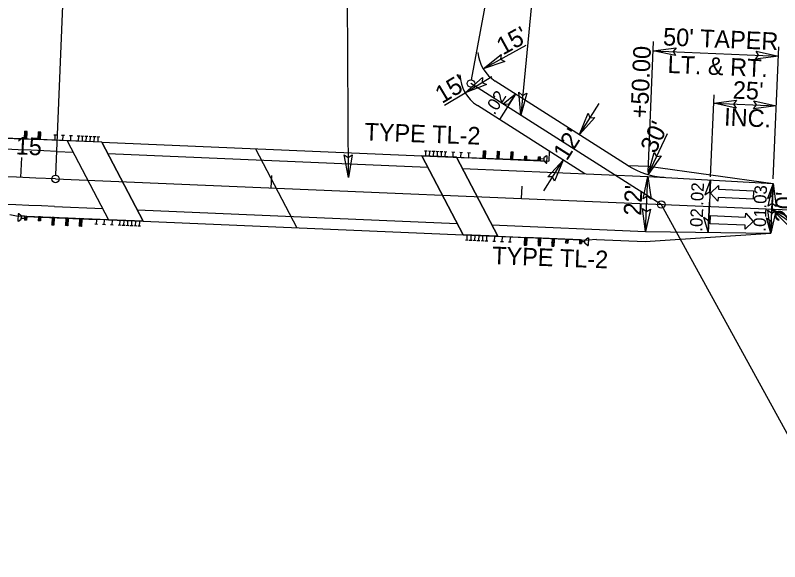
# Model space of a CAD drawing. Extents: x 2170295 to 2171718, y 723585 to 724580.
# Drawn here: x 2170898.6 to 2171203.6, y 723922.2 to 724140.1 of the extents above; entities that cross this region are included whole.
import ezdxf

# ---------------------------------------------------------------- set-up
doc = ezdxf.new("R2010")
doc.units = 0
for name, color, linetype in [('Prop Approach Slab', 7, 'Continuous'), ('Prop Approach Slab Hatching', 7, 'Continuous'), ('Prop Dimension', 7, 'Continuous'), ('Prop DSN Text', 7, 'Continuous'), ('Prop EOT', 7, 'Continuous'), ('Prop Guardrail', 7, 'Continuous'), ('Prop Guardrail Anchor Unit CELL', 7, 'Continuous'), ('Prop Horizontal Alignment', 7, 'Continuous'), ('Prop Horizontal Alignment Direction Label', 7, 'Continuous'), ('Prop Horizontal Alignment Station Label', 7, 'Continuous'), ('Prop Horizontal Alignment Tick Label', 7, 'Continuous'), ('Prop Horizontal Alignment Tick Large', 7, 'Continuous'), ('Prop Horizontal Alignment Tick Small', 7, 'Continuous'), ('Prop Lane Arrow CELL', 7, 'Continuous'), ('Prop Paved Shoulder', 7, 'Continuous'), ('Prop Roadway Bridge', 7, 'Continuous'), ('Prop Structure Anchor Unit CELL', 7, 'Continuous'), ('Prop Superelevation  Arrow CELL', 7, 'Continuous'), ('Prop Superelevation Label', 7, 'Continuous'), ('Prop Terminator CELL', 7, 'Continuous')]:
    doc.layers.add(name, color=color, linetype=linetype)

msp = doc.modelspace()

# ---------------------------------------------------------------- linework, layer by layer
at = {"layer": 'Prop Approach Slab'}
for p, q in [((2170933.16, 724089.46), (2170919.32, 724090.04)), ((2170919.32, 724090.04), (2170935.81, 724058.48)), ((2171060.1, 724084.1), (2171060.1, 724084.1)), ((2171060.79, 724084.07), (2171074.62, 724083.48)), ((2171074.62, 724083.48), (2171091.11, 724051.93)), ((2170949.64, 724057.9), (2170935.81, 724058.48)), ((2171091.11, 724051.93), (2171077.27, 724052.51))]:
    msp.add_line(p, q, dxfattribs=at)
at = {"layer": 'Prop Approach Slab Hatching'}
for points in [[(2170935.81, 724058.48), (2170949.64, 724057.9), (2170933.16, 724089.46), (2170919.32, 724090.04)], [(2171074.62, 724083.48), (2171060.79, 724084.07), (2171077.27, 724052.51), (2171091.11, 724051.93)]]:
    msp.add_lwpolyline(points, close=True, dxfattribs=at)
at = {"layer": 'Prop Dimension'}
for p, q in [((2171031.51, 724075.41), (2171030.57, 724264.51)), ((2171151.12, 724077.55), (2171153.32, 724129.63)), ((2171085.32, 724118.69), (2171102.5, 724128.16)), ((2171153.16, 724125.94), (2171203.12, 724123.83)), ((2171201.05, 724074.86), (2171203.28, 724127.52)), ((2171078.07, 724109.2), (2171088.79, 724115.68)), ((2171069.84, 724104.23), (2171078.07, 724109.2)), ((2171176.06, 724075.65), (2171177.44, 724108.29)), ((2171123.68, 724092.47), (2171131.54, 724104.86)), ((2171177.3, 724105.02), (2171202.28, 724103.96)), ((2171151.08, 724076.55), (2171158.83, 724092.95)), ((2171109.43, 724070.04), (2171117.25, 724082.34)), ((2171200.14, 724053.22), (2171200.97, 724072.93)), ((2171200.54, 724062.74), (2171439.97, 723895.67))]:
    msp.add_line(p, q, dxfattribs=at)
at = {"layer": 'Prop DSN Text'}
msp.add_line((2171150.12, 724053.86), (2171151.05, 724075.84), dxfattribs=at)
msp.add_line((2171150.12, 724053.86), (2171151.05, 724075.84), dxfattribs=at)
msp.add_line((2171150.12, 724053.86), (2171151.05, 724075.84), dxfattribs=at)
at = {"layer": 'Prop EOT'}
for p, q in [((2171143.19, 724080.08), (2171090.12, 724113.78)), ((2171125.82, 724076.9), (2171082.98, 724104.1)), ((2170915.08, 724085.8), (2170921.68, 724085.52)), ((2171076.98, 724078.96), (2171151.05, 724075.84)), ((2171151.05, 724075.84), (2171200.97, 724072.93)), ((2170914.15, 724063.82), (2170933.44, 724063)), ((2171088.75, 724056.45), (2171150.12, 724053.86)), ((2171150.12, 724053.86), (2171200.14, 724053.22))]:
    msp.add_line(p, q, dxfattribs=at)
for centre, radius, start, end in [((2171098.16, 724126.45), 15, 184.6964, 237.5825), ((2171091.02, 724116.76), 15, 181.901, 237.5825), ((2168445.99, 665601.01), 58536.88, 87.5825428, 87.7429222), ((2171159.27, 724105.41), 30, 237.5825, 266.6634), ((2168445.99, 665601.01), 58514.88, 87.5825428, 87.7429222)]:
    msp.add_arc(centre, radius, start, end, dxfattribs=at)
at = {"layer": 'Prop Guardrail'}
for p, q in [((2170914.43, 724090.25), (2170908.18, 724090.51)), ((2171085.76, 724083.01), (2171079.52, 724083.28)), ((2170924.67, 724058.95), (2170930.91, 724058.69)), ((2171096, 724051.72), (2171102.25, 724051.46))]:
    msp.add_line(p, q, dxfattribs=at)
at = {"layer": 'Prop Guardrail Anchor Unit CELL'}
for p, q in [((2170902.26, 724090.76), (2170902.38, 724093.79)), ((2170903.2, 724092.24), (2170902.26, 724090.76)), ((2170902.32, 724092.28), (2170903.26, 724093.76)), ((2170903.2, 724092.24), (2170902.32, 724092.28)), ((2170903.13, 724090.72), (2170902.32, 724092.28)), ((2170903.26, 724093.76), (2170902.38, 724093.79)), ((2170902.38, 724093.79), (2170903.2, 724092.24)), ((2170903.13, 724090.72), (2170903.26, 724093.76)), ((2170907.74, 724090.53), (2170907.87, 724093.56)), ((2170908.68, 724092.01), (2170907.74, 724090.53)), ((2170907.81, 724092.05), (2170908.75, 724093.52)), ((2170908.68, 724092.01), (2170907.81, 724092.05)), ((2170908.62, 724090.49), (2170907.81, 724092.05)), ((2170908.75, 724093.52), (2170907.87, 724093.56)), ((2170907.87, 724093.56), (2170908.68, 724092.01)), ((2170908.62, 724090.49), (2170908.75, 724093.52)), ((2170886.24, 724091.44), (2170908.18, 724090.51)), ((2170903.13, 724090.72), (2170902.26, 724090.76)), ((2170908.62, 724090.49), (2170907.74, 724090.53)), ((2171085.32, 724083.03), (2171085.45, 724086.06)), ((2171086.33, 724086.03), (2171085.39, 724084.55)), ((2171086.27, 724084.51), (2171085.45, 724086.06)), ((2171085.45, 724086.06), (2171086.33, 724086.03)), ((2171086.2, 724082.99), (2171086.33, 724086.03)), ((2171090.81, 724082.8), (2171090.94, 724085.83)), ((2171091.82, 724085.8), (2171090.87, 724084.32)), ((2171091.75, 724084.28), (2171090.94, 724085.83)), ((2171090.94, 724085.83), (2171091.82, 724085.8)), ((2171091.69, 724082.76), (2171091.82, 724085.8)), ((2171096.3, 724082.57), (2171096.42, 724085.6)), ((2171097.3, 724085.56), (2171096.36, 724084.09)), ((2171097.24, 724084.05), (2171096.42, 724085.6)), ((2171096.42, 724085.6), (2171097.3, 724085.56)), ((2171097.17, 724082.53), (2171097.3, 724085.56)), ((2171085.32, 724083.03), (2171086.27, 724084.51)), ((2171085.32, 724083.03), (2171086.2, 724082.99)), ((2171085.39, 724084.55), (2171086.27, 724084.51)), ((2171085.39, 724084.55), (2171086.2, 724082.99)), ((2171107.71, 724082.09), (2171085.76, 724083.01)), ((2171090.81, 724082.8), (2171091.75, 724084.28)), ((2171090.81, 724082.8), (2171091.69, 724082.76)), ((2171090.87, 724084.32), (2171091.75, 724084.28)), ((2171090.87, 724084.32), (2171091.69, 724082.76)), ((2171096.3, 724082.57), (2171097.24, 724084.05)), ((2171096.3, 724082.57), (2171097.17, 724082.53)), ((2171096.36, 724084.09), (2171097.24, 724084.05)), ((2171096.36, 724084.09), (2171097.17, 724082.53)), ((2171101.78, 724082.34), (2171101.85, 724083.85)), ((2171101.78, 724082.34), (2171102.73, 724083.82)), ((2171101.85, 724083.85), (2171102.72, 724083.82)), ((2171101.85, 724083.85), (2171102.66, 724082.3)), ((2171102.66, 724082.3), (2171102.72, 724083.82)), ((2171107.27, 724082.11), (2171107.33, 724083.62)), ((2171107.27, 724082.11), (2171108.21, 724083.58)), ((2171107.33, 724083.62), (2171108.21, 724083.58)), ((2171107.33, 724083.62), (2171108.15, 724082.07)), ((2171108.15, 724082.07), (2171108.21, 724083.58)), ((2171109.47, 724082.75), (2171108.18, 724082.8)), ((2171109.49, 724083.25), (2171109.44, 724082.03)), ((2171110.56, 724084.06), (2171109.49, 724083.25)), ((2171110.56, 724084.06), (2171110.83, 724084.05)), ((2171110.71, 724081.11), (2171110.83, 724084.05)), ((2171101.78, 724082.34), (2171102.66, 724082.3)), ((2171107.27, 724082.11), (2171108.15, 724082.07)), ((2171108.15, 724082.08), (2171109.44, 724082.03)), ((2171109.44, 724082.03), (2171110.44, 724081.12)), ((2171110.44, 724081.12), (2171110.71, 724081.11)), ((2170899.72, 724060.85), (2170899.6, 724057.92)), ((2170899.99, 724060.84), (2170899.72, 724060.85)), ((2170899.87, 724057.9), (2170900.94, 724058.72)), ((2170900.99, 724059.94), (2170899.99, 724060.84)), ((2170900.94, 724058.72), (2170900.99, 724059.94)), ((2170900.96, 724059.22), (2170902.25, 724059.17)), ((2170902.28, 724059.89), (2170900.99, 724059.94)), ((2170902.28, 724059.9), (2170902.22, 724058.38)), ((2170903.16, 724059.86), (2170902.22, 724058.38)), ((2170903.1, 724058.34), (2170902.22, 724058.38)), ((2170903.16, 724059.86), (2170902.28, 724059.9)), ((2170903.1, 724058.34), (2170902.28, 724059.9)), ((2170902.72, 724059.88), (2170924.67, 724058.95)), ((2170903.16, 724059.86), (2170903.1, 724058.34)), ((2170907.77, 724059.67), (2170907.7, 724058.15)), ((2170908.65, 724059.63), (2170907.7, 724058.15)), ((2170908.58, 724058.11), (2170907.7, 724058.15)), ((2170908.65, 724059.63), (2170907.77, 724059.67)), ((2170908.58, 724058.11), (2170907.77, 724059.67)), ((2170908.65, 724059.63), (2170908.58, 724058.11)), ((2170913.25, 724059.44), (2170913.13, 724056.4)), ((2170914.13, 724059.4), (2170913.19, 724057.92)), ((2170914.13, 724059.4), (2170913.25, 724059.44)), ((2170914.07, 724057.88), (2170913.25, 724059.44)), ((2170914.13, 724059.4), (2170914, 724056.37)), ((2170918.74, 724059.2), (2170918.61, 724056.17)), ((2170919.62, 724059.17), (2170918.68, 724057.69)), ((2170919.62, 724059.17), (2170918.74, 724059.2)), ((2170919.55, 724057.65), (2170918.74, 724059.2)), ((2170919.62, 724059.17), (2170919.49, 724056.13)), ((2170924.23, 724058.97), (2170924.1, 724055.94)), ((2170925.11, 724058.93), (2170924.16, 724057.45)), ((2170925.11, 724058.93), (2170924.23, 724058.97)), ((2170925.04, 724057.42), (2170924.23, 724058.97)), ((2170925.11, 724058.93), (2170924.98, 724055.9)), ((2170899.87, 724057.9), (2170899.6, 724057.92)), ((2170913.13, 724056.4), (2170914.07, 724057.88)), ((2170914, 724056.37), (2170913.13, 724056.4)), ((2170914.07, 724057.88), (2170913.19, 724057.92)), ((2170913.19, 724057.92), (2170914, 724056.37)), ((2170918.61, 724056.17), (2170919.55, 724057.65)), ((2170919.49, 724056.13), (2170918.61, 724056.17)), ((2170919.55, 724057.65), (2170918.68, 724057.69)), ((2170918.68, 724057.69), (2170919.49, 724056.13)), ((2170924.1, 724055.94), (2170925.04, 724057.42)), ((2170924.98, 724055.9), (2170924.1, 724055.94)), ((2170925.04, 724057.42), (2170924.16, 724057.45)), ((2170924.16, 724057.45), (2170924.98, 724055.9)), ((2171101.81, 724051.47), (2171101.68, 724048.44)), ((2171102.62, 724049.92), (2171101.68, 724048.44)), ((2171101.75, 724049.96), (2171102.69, 724051.44)), ((2171101.75, 724049.96), (2171102.62, 724049.92)), ((2171102.56, 724048.4), (2171101.75, 724049.96)), ((2171101.81, 724051.47), (2171102.69, 724051.44)), ((2171101.81, 724051.47), (2171102.62, 724049.92)), ((2171124.19, 724050.53), (2171102.25, 724051.46)), ((2171102.69, 724051.44), (2171102.56, 724048.4)), ((2171107.3, 724051.24), (2171107.17, 724048.21)), ((2171108.11, 724049.69), (2171107.17, 724048.21)), ((2171107.23, 724049.73), (2171108.17, 724051.21)), ((2171107.23, 724049.73), (2171108.11, 724049.69)), ((2171108.05, 724048.17), (2171107.23, 724049.73)), ((2171107.3, 724051.24), (2171108.17, 724051.21)), ((2171107.3, 724051.24), (2171108.11, 724049.69)), ((2171108.17, 724051.21), (2171108.05, 724048.17)), ((2171112.78, 724051.01), (2171112.65, 724047.98)), ((2171113.6, 724049.46), (2171112.65, 724047.98)), ((2171112.72, 724049.49), (2171113.66, 724050.97)), ((2171112.72, 724049.49), (2171113.6, 724049.46)), ((2171113.53, 724047.94), (2171112.72, 724049.49)), ((2171112.78, 724051.01), (2171113.66, 724050.97)), ((2171112.78, 724051.01), (2171113.6, 724049.46)), ((2171113.66, 724050.97), (2171113.53, 724047.94)), ((2171118.27, 724050.78), (2171118.2, 724049.26)), ((2171118.2, 724049.26), (2171119.15, 724050.74)), ((2171118.2, 724049.26), (2171119.08, 724049.23)), ((2171118.27, 724050.78), (2171119.15, 724050.74)), ((2171118.27, 724050.78), (2171119.08, 724049.23)), ((2171119.15, 724050.74), (2171119.08, 724049.23)), ((2171123.75, 724050.55), (2171123.69, 724049.03)), ((2171123.69, 724049.03), (2171124.63, 724050.51)), ((2171123.69, 724049.03), (2171124.57, 724048.99)), ((2171123.75, 724050.55), (2171124.63, 724050.51)), ((2171123.75, 724050.55), (2171124.57, 724048.99)), ((2171124.63, 724050.51), (2171124.57, 724048.99)), ((2171125.89, 724049.72), (2171124.6, 724049.78)), ((2171124.63, 724050.5), (2171125.92, 724050.44)), ((2171125.87, 724049.22), (2171125.92, 724050.44)), ((2171126.87, 724048.32), (2171125.87, 724049.22)), ((2171125.92, 724050.44), (2171126.99, 724051.26)), ((2171126.99, 724051.26), (2171127.26, 724051.25)), ((2171127.26, 724051.25), (2171127.13, 724048.31)), ((2171101.68, 724048.44), (2171102.56, 724048.4)), ((2171107.17, 724048.21), (2171108.05, 724048.17)), ((2171112.65, 724047.98), (2171113.53, 724047.94)), ((2171126.87, 724048.32), (2171127.13, 724048.31))]:
    msp.add_line(p, q, dxfattribs=at)
at = {"layer": 'Prop Horizontal Alignment'}
for p, q in [((2171156.38, 724064.6), (2171080.4, 724112.85)), ((2170914.62, 724074.81), (2171360.17, 724056))]:
    msp.add_line(p, q, dxfattribs=at)
msp.add_arc((2168445.99, 665601.01), 58525.88, 87.5825428, 88.0715445, dxfattribs=at)
at = {"layer": 'Prop Horizontal Alignment Direction Label'}
msp.add_line((2171111.26, 724212.03), (2171100.26, 724100.24), dxfattribs=at)
at = {"layer": 'Prop Horizontal Alignment Station Label'}
for p, q in [((2170914.68, 724076.31), (2170926.22, 724349.56)), ((2171080.67, 724114.32), (2171109.24, 724269.49)), ((2171156.38, 724064.6), (2171224.4, 723940.64))]:
    msp.add_line(p, q, dxfattribs=at)
for centre in [(2171080.4, 724112.85), (2170914.62, 724074.81), (2171156.38, 724064.6)]:
    msp.add_circle(centre, 1.5, dxfattribs=at)
at = {"layer": 'Prop Horizontal Alignment Tick Large'}
msp.add_line((2170900.81, 724075.39), (2170901.14, 724083.38), dxfattribs=at)
at = {"layer": 'Prop Horizontal Alignment Tick Small'}
for p, q in [((2171000.72, 724071.17), (2171000.93, 724076.17)), ((2171100.63, 724066.95), (2171100.84, 724071.95)), ((2171200.54, 724062.74), (2171200.75, 724067.73))]:
    msp.add_line(p, q, dxfattribs=at)
at = {"layer": 'Prop Lane Arrow CELL'}
for p, q in [((2171175.95, 724069.11), (2171179.23, 724072.17)), ((2171179.23, 724072.17), (2171179.16, 724070.67)), ((2171179.16, 724070.67), (2171193.15, 724070.08)), ((2171178.96, 724065.88), (2171175.95, 724069.11)), ((2171179.03, 724067.37), (2171178.96, 724065.88)), ((2171193.01, 724066.78), (2171179.03, 724067.37)), ((2171193.15, 724070.08), (2171193.01, 724066.78)), ((2171190.01, 724059.61), (2171190.07, 724061.11)), ((2171190.07, 724061.11), (2171193.09, 724057.88)), ((2171175.88, 724056.9), (2171176.02, 724060.2)), ((2171176.02, 724060.2), (2171190.01, 724059.61)), ((2171189.87, 724056.31), (2171175.88, 724056.9)), ((2171193.09, 724057.88), (2171189.81, 724054.81)), ((2171189.81, 724054.81), (2171189.87, 724056.31))]:
    msp.add_line(p, q, dxfattribs=at)
at = {"layer": 'Prop Paved Shoulder'}
for p, q in [((2171083.46, 724122.19), (2171083.46, 724122.19)), ((2170919.32, 724090.04), (2170883.2, 724091.56)), ((2171111.61, 724085.93), (2171111.44, 724081.93)), ((2171074.62, 724083.48), (2171111.44, 724081.93)), ((2171143.04, 724080.18), (2171151.22, 724079.83)), ((2171151.07, 724079.84), (2171151.22, 724079.83)), ((2171151.22, 724079.83), (2171200.97, 724072.93)), ((2170896.38, 724060.56), (2170899.69, 724060.01)), ((2170935.81, 724058.48), (2170899.69, 724060.01)), ((2171149.95, 724049.86), (2171200.14, 724053.22)), ((2171091.11, 724051.93), (2171127.23, 724050.4)), ((2171130.57, 724050.68), (2171127.23, 724050.4)), ((2171130.57, 724050.68), (2171149.95, 724049.86))]:
    msp.add_line(p, q, dxfattribs=at)
at = {"layer": 'Prop Roadway Bridge'}
for p, q in [((2170933.16, 724089.46), (2171060.79, 724084.07)), ((2170933.16, 724089.46), (2170949.64, 724057.9)), ((2170933.16, 724089.46), (2170949.64, 724057.9)), ((2170994.47, 724086.87), (2171010.96, 724055.31)), ((2170935.52, 724084.94), (2171063.15, 724079.55)), ((2171077.27, 724052.51), (2171060.79, 724084.07)), ((2171060.79, 724084.07), (2171077.27, 724052.51)), ((2170947.28, 724062.42), (2171074.91, 724057.03)), ((2170949.64, 724057.9), (2171077.27, 724052.51))]:
    msp.add_line(p, q, dxfattribs=at)
at = {"layer": 'Prop Structure Anchor Unit CELL'}
for p, q in [((2170915.08, 724092.22), (2170913.94, 724092.27)), ((2170914.43, 724090.25), (2170914.51, 724092.24)), ((2170918.2, 724092.09), (2170917.06, 724092.14)), ((2170917.55, 724090.11), (2170917.63, 724092.11)), ((2170921.33, 724091.96), (2170920.18, 724092.01)), ((2170920.67, 724089.98), (2170920.75, 724091.98)), ((2170924.45, 724091.83), (2170923.3, 724091.87)), ((2170923.79, 724089.85), (2170923.88, 724091.85)), ((2170926.01, 724091.76), (2170924.87, 724091.81)), ((2170925.35, 724089.79), (2170925.44, 724091.78)), ((2170927.57, 724091.69), (2170926.43, 724091.74)), ((2170926.91, 724089.72), (2170927, 724091.72)), ((2170929.13, 724091.63), (2170927.99, 724091.68)), ((2170928.48, 724089.65), (2170928.56, 724091.65)), ((2170930.69, 724091.56), (2170929.55, 724091.61)), ((2170933.16, 724089.46), (2170914.43, 724090.25)), ((2170930.04, 724089.59), (2170930.12, 724091.59)), ((2170932.25, 724091.5), (2170931.11, 724091.54)), ((2170931.6, 724089.52), (2170931.68, 724091.52)), ((2171061.86, 724086.02), (2171063, 724085.98)), ((2171062.35, 724084), (2171062.43, 724086)), ((2171063.42, 724085.96), (2171064.56, 724085.91)), ((2171063.91, 724083.94), (2171063.99, 724085.93)), ((2171064.98, 724085.89), (2171066.12, 724085.84)), ((2171065.47, 724083.87), (2171065.55, 724085.87)), ((2171066.54, 724085.83), (2171067.69, 724085.78)), ((2171067.03, 724083.8), (2171067.11, 724085.8)), ((2171068.1, 724085.76), (2171069.25, 724085.71)), ((2171068.59, 724083.74), (2171068.67, 724085.74)), ((2171069.66, 724085.69), (2171070.81, 724085.65)), ((2171070.15, 724083.67), (2171070.24, 724085.67)), ((2171072.79, 724085.56), (2171073.93, 724085.51)), ((2171073.27, 724083.54), (2171073.36, 724085.54)), ((2171060.79, 724084.07), (2171079.52, 724083.28)), ((2171075.91, 724085.43), (2171077.05, 724085.38)), ((2171076.4, 724083.41), (2171076.48, 724085.41)), ((2171079.03, 724085.3), (2171080.17, 724085.25)), ((2171079.52, 724083.28), (2171079.6, 724085.27)), ((2170930.91, 724058.69), (2170930.83, 724056.69)), ((2170949.64, 724057.9), (2170930.91, 724058.69)), ((2170934.03, 724058.56), (2170933.95, 724056.56)), ((2170937.16, 724058.43), (2170937.07, 724056.43)), ((2170940.28, 724058.29), (2170940.19, 724056.3)), ((2170941.84, 724058.23), (2170941.75, 724056.23)), ((2170943.4, 724058.16), (2170943.32, 724056.16)), ((2170944.96, 724058.1), (2170944.88, 724056.1)), ((2170931.4, 724056.67), (2170930.25, 724056.72)), ((2170934.52, 724056.54), (2170933.38, 724056.58)), ((2170937.64, 724056.4), (2170936.5, 724056.45)), ((2170940.77, 724056.27), (2170939.62, 724056.32)), ((2170942.33, 724056.21), (2170941.18, 724056.25)), ((2170943.89, 724056.14), (2170942.74, 724056.19)), ((2170945.45, 724056.07), (2170944.3, 724056.12)), ((2170947.01, 724056.01), (2170945.87, 724056.06)), ((2170946.52, 724058.03), (2170946.44, 724056.03)), ((2170948.57, 724055.94), (2170947.43, 724055.99)), ((2170948.08, 724057.96), (2170948, 724055.97)), ((2171077.27, 724052.51), (2171096, 724051.72)), ((2171078.83, 724052.44), (2171078.75, 724050.45)), ((2171080.39, 724052.38), (2171080.31, 724050.38)), ((2171081.95, 724052.31), (2171081.87, 724050.31)), ((2171083.51, 724052.25), (2171083.43, 724050.25)), ((2171085.08, 724052.18), (2171084.99, 724050.18)), ((2171086.64, 724052.12), (2171086.55, 724050.12)), ((2171089.76, 724051.98), (2171089.67, 724049.99)), ((2171078.17, 724050.47), (2171079.32, 724050.42)), ((2171079.74, 724050.4), (2171080.88, 724050.36)), ((2171081.3, 724050.34), (2171082.44, 724050.29)), ((2171082.86, 724050.27), (2171084, 724050.22)), ((2171084.42, 724050.21), (2171085.56, 724050.16)), ((2171085.98, 724050.14), (2171087.12, 724050.09)), ((2171089.1, 724050.01), (2171090.25, 724049.96)), ((2171092.22, 724049.88), (2171093.37, 724049.83)), ((2171092.88, 724051.85), (2171092.8, 724049.85)), ((2171095.35, 724049.75), (2171096.49, 724049.7)), ((2171096, 724051.72), (2171095.92, 724049.72))]:
    msp.add_line(p, q, dxfattribs=at)
at = {"layer": 'Prop Superelevation  Arrow CELL'}
for p, q in [((2171098.2, 724108.66), (2171091.76, 724098.53)), ((2171176.01, 724074.38), (2171175.5, 724062.39)), ((2171200.97, 724072.93), (2171200.46, 724060.94)), ((2171175.13, 724053.54), (2171175.64, 724065.53)), ((2171200.14, 724053.22), (2171200.64, 724065.21))]:
    msp.add_line(p, q, dxfattribs=at)
for points in [[(2171098.2, 724108.66), (2171093.29, 724104.66), (2171095.72, 724104.75)], [(2171176.01, 724074.38), (2171173.76, 724068.47), (2171175.81, 724069.76)], [(2171200.97, 724072.93), (2171198.72, 724067.02), (2171200.78, 724068.3)], [(2171175.13, 724053.54), (2171173.38, 724059.61), (2171175.32, 724058.16)], [(2171200.14, 724053.22), (2171198.39, 724059.29), (2171200.33, 724057.84)]]:
    msp.add_lwpolyline(points, close=True, dxfattribs=at)
at = {"layer": 'Prop Superelevation Label'}
for p, q in [((2171176.01, 724074.38), (2171175.13, 724053.54)), ((2171200.14, 724053.22), (2171200.97, 724072.93))]:
    msp.add_line(p, q, dxfattribs=at)
at = {"layer": 'Prop Terminator CELL'}
for points in [[(2171162.09, 724124.01), (2171153.16, 724125.94), (2171162.27, 724127.15), (2171161.06, 724125.6)], [(2171194.19, 724125.75), (2171203.12, 724123.83), (2171194.01, 724122.61), (2171195.23, 724124.16)], [(2171093.95, 724121.68), (2171085.32, 724118.69), (2171092.48, 724124.46), (2171092.24, 724122.51)], [(2171086.57, 724112.53), (2171078.07, 724109.2), (2171084.99, 724115.25), (2171084.83, 724113.29)], [(2171102.69, 724109.04), (2171100.26, 724100.24), (2171099.56, 724109.4), (2171101.04, 724108.1)], [(2171186.23, 724103.09), (2171177.3, 724105.02), (2171186.41, 724106.23), (2171185.2, 724104.68)], [(2171193.35, 724105.89), (2171202.28, 724103.96), (2171193.17, 724102.75), (2171194.39, 724104.3)], [(2171129.81, 724099.24), (2171123.68, 724092.47), (2171127.18, 724100.97), (2171127.91, 724099.14)], [(2171033.02, 724084.42), (2171031.51, 724075.41), (2171029.87, 724084.46), (2171031.47, 724083.31)], [(2171156.32, 724084.02), (2171151.08, 724076.55), (2171153.5, 724085.41), (2171154.45, 724083.69)], [(2171111.11, 724075.58), (2171117.25, 724082.34), (2171113.75, 724073.85), (2171113.01, 724075.67)], [(2171149.12, 724066.91), (2171151.05, 724075.84), (2171152.27, 724066.73), (2171150.72, 724067.94)], [(2171199.04, 724064), (2171200.97, 724072.93), (2171202.19, 724063.82), (2171200.64, 724065.03)], [(2171152.05, 724062.78), (2171150.12, 724053.86), (2171148.9, 724062.97), (2171150.45, 724061.75)], [(2171202.07, 724062.14), (2171200.14, 724053.22), (2171198.92, 724062.33), (2171200.47, 724061.11)], [(2171213.53, 724049.89), (2171200.54, 724062.74), (2171217.22, 724055), (2171213.5, 724053.7)]]:
    msp.add_lwpolyline(points, close=True, dxfattribs=at)

# ---------------------------------------------------------------- texts
at = {"layer": 'Prop DSN Text'}
for s, rotation, p in [("15'", 28.8848, (2171093.12, 724123.99)), ("50' TAPER", 357.5825, (2171156.98, 724128.08)), ('+50.00', 87.5825, (2171151.05, 724098.84)), ('LT. & RT.', 357.5825, (2171158.77, 724117.09)), ("15'", 31.1395, (2171068.86, 724104.67)), ("25'", 357.5825, (2171184.8, 724106.85)), ('INC.', 357.5825, (2171181.34, 724096.1)), ("30'", 64.7131, (2171154.01, 724084.59)), ('TYPE TL-2', 357.8574, (2171037.82, 724090.19)), ("12'", 57.5825, (2171118.66, 724081.71)), ("22'", 87.5825, (2171148.35, 724060.03)), ("20'", 87.5825, (2171208.69, 724057.32)), ('TYPE TL-2', 357.8574, (2171088.78, 724040.85))]:
    msp.add_text(s, height=7, rotation=rotation, dxfattribs=at).set_placement(p)
at = {"layer": 'Prop Horizontal Alignment Tick Label'}
msp.add_text('15', height=7, rotation=357.5961, dxfattribs=at).set_placement((2170898.63, 724084.61))
at = {"layer": 'Prop Superelevation Label'}
for s, rotation, p in [('.02', 57.5825, (2171089.78, 724100.09)), ('.02', 87.5825, (2171173.05, 724064.01)), ('.03', 87.5825, (2171198.22, 724062.93)), ('.02', 87.5825, (2171172.73, 724053.7)), ('.01', 87.5825, (2171198.01, 724053.72))]:
    msp.add_text(s, height=5, rotation=rotation, dxfattribs=at).set_placement(p)

doc.saveas('drawing.dxf')
